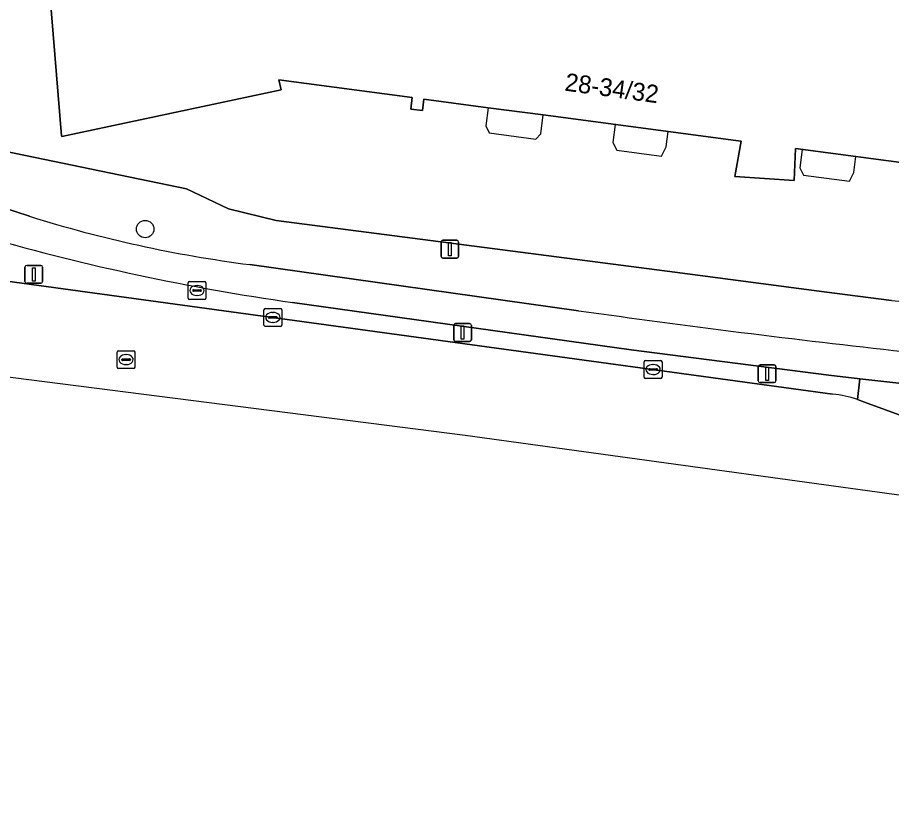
# Model space of a CAD drawing. Extents: x 160675 to 161153, y 383241 to 383714.
# Drawn here: x 160724.18 to 160773.22, y 383263.09 to 383306.84 of the extents above; entities that cross this region are included whole.
import ezdxf

# ---------------------------------------------------------------- set-up
doc = ezdxf.new("R2010")
doc.units = 0
for name, color, linetype in [('IMGEO_Berm_open', 7, 'Continuous'), ('IMGEO_Boom', 7, 'Continuous'), ('IMGEO_Fietspad_gesloten', 7, 'Continuous'), ('IMGEO_Groenvoorziening', 7, 'Continuous'), ('IMGEO_Kolk', 7, 'Continuous'), ('IMGEO_Lichtmast', 7, 'Continuous'), ('IMGEO_Pand', 7, 'Continuous'), ('IMGEO_Pand_nummerreeks', 7, 'Continuous'), ('IMGEO_Pand_overbouw', 7, 'Continuous'), ('IMGEO_Rijbaan_lokaal_gesloten', 7, 'Continuous'), ('IMGEO_Rioolput', 7, 'Continuous'), ('IMGEO_Voetpad_open', 7, 'Continuous')]:
    doc.layers.add(name, color=color, linetype=linetype)

msp = doc.modelspace()

# ---------------------------------------------------------------- linework, layer by layer
at = {"layer": 'IMGEO_Berm_open'}
for points in [[(160720.857, 383292.423), (160769.912, 383285.718)], [(160771.308, 383285.419), (160771.45, 383286.574), (160769.706, 383286.77), (160758.605, 383288.201), (160739.615, 383290.854)]]:
    msp.add_lwpolyline(points, dxfattribs=at)
for centre, radius, start, end in [((160757.689, 383417.561), 127.99, 254.03333, 261.88177), ((160769.234, 383279.143), 6.61, 71.7112, 84.1105)]:
    msp.add_arc(centre, radius, start, end, dxfattribs=at)
at = {"layer": 'IMGEO_Boom'}
msp.add_circle((160731.347, 383294.972), 0.489, dxfattribs=at)
at = {"layer": 'IMGEO_Fietspad_gesloten'}
for points in [[(160724.863, 383295.69), (160719.204, 383297.531)], [(160755.662, 383290.395), (160737.228, 383292.98)], [(160739.615, 383290.854), (160758.605, 383288.201), (160769.706, 383286.77), (160771.45, 383286.574), (160777.852, 383285.853), (160783.082, 383285.264), (160794.632, 383283.749), (160799.634, 383283.067), (160810.848, 383281.538), (160816.508, 383280.767), (160828.488, 383279.134), (160834.185, 383278.357), (160852.13, 383275.911), (160857.577, 383275.169), (160873.203, 383273.039)]]:
    msp.add_lwpolyline(points, dxfattribs=at)
for centre, radius, start, end in [((160746.363, 383364.222), 71.826, 252.58268, 262.69355), ((160757.689, 383417.561), 127.99, 254.03333, 261.88177), ((160838.878, 383879.339), 594.794, 261.957551, 263.729038)]:
    msp.add_arc(centre, radius, start, end, dxfattribs=at)
at = {"layer": 'IMGEO_Groenvoorziening'}
for points in [[(160774.882, 383298.555), (160767.84, 383299.49), (160767.765, 383297.687), (160764.421, 383297.914), (160764.421, 383297.916), (160764.788, 383299.895), (160764.483, 383299.936), (160753.68, 383301.37), (160750.598, 383301.779), (160746.986, 383302.258), (160746.904, 383301.62), (160746.246, 383301.706), (160746.332, 383302.345), (160738.853, 383303.338), (160738.971, 383302.787), (160726.669, 383300.167), (160726.644, 383300.199), (160724.272, 383329.175)], [(160720.042, 383300.069), (160720.82, 383299.881), (160733.661, 383297.23), (160736.023, 383296.113), (160738.693, 383295.459), (160761.067, 383292.551), (160769.45, 383291.461), (160773.221, 383290.971)]]:
    msp.add_lwpolyline(points, dxfattribs=at)
msp.add_lwpolyline([(160777.852, 383285.853), (160771.45, 383286.574), (160771.308, 383285.419), (160771.71, 383285.271), (160777.187, 383283.264), (160777.552, 383283.158)], close=True, dxfattribs=at)
msp.add_arc((160774.582, 383301.91), 11.023, 262.9096, 313.4171, dxfattribs=at)
at = {"layer": 'IMGEO_Kolk'}
for p, q in [((160738.011, 383289.59), (160738.011, 383290.442)), ((160738.086, 383290.516), (160738.938, 383290.516)), ((160739.012, 383290.442), (160739.012, 383289.59)), ((160738.27, 383290.01), (160738.27, 383290.022)), ((160738.708, 383289.973), (160738.31, 383289.973)), ((160738.313, 383290.059), (160738.711, 383290.059)), ((160738.499, 383290.296), (160738.524, 383290.296)), ((160738.754, 383290.022), (160738.754, 383290.01)), ((160738.938, 383289.516), (160738.086, 383289.516)), ((160738.522, 383289.736), (160738.497, 383289.736)), ((160759.344, 383286.669), (160759.344, 383287.521)), ((160759.419, 383287.595), (160760.271, 383287.595)), ((160760.345, 383287.521), (160760.345, 383286.669)), ((160759.603, 383287.089), (160759.603, 383287.101)), ((160760.041, 383287.052), (160759.643, 383287.052)), ((160759.646, 383287.138), (160760.044, 383287.138)), ((160759.832, 383287.375), (160759.857, 383287.375)), ((160760.087, 383287.101), (160760.087, 383287.089)), ((160760.271, 383286.595), (160759.419, 383286.595)), ((160759.855, 383286.815), (160759.83, 383286.815))]:
    msp.add_line(p, q, dxfattribs=at)
for points in [[(160738.011, 383289.59), (160738.011, 383290.442)], [(160738.086, 383290.516), (160738.938, 383290.516)], [(160739.012, 383290.442), (160739.012, 383289.59)], [(160738.938, 383289.516), (160738.086, 383289.516)], [(160759.344, 383286.669), (160759.344, 383287.521)], [(160759.419, 383287.595), (160760.271, 383287.595)], [(160760.345, 383287.521), (160760.345, 383286.669)], [(160760.271, 383286.595), (160759.419, 383286.595)]]:
    msp.add_lwpolyline(points, dxfattribs=at)
for centre, radius, start, end in [((160738.088, 383290.44), 0.0765, 91.552, 178.448), ((160738.088, 383290.44), 0.0765, 91.552, 178.448), ((160738.936, 383290.44), 0.0765, 1.552, 88.448), ((160738.936, 383290.44), 0.0765, 1.552, 88.448), ((160738.31, 383290.019), 0.0403, 85.8775, 175.7526), ((160738.307, 383290.009), 0.0366, 178.938, 274.7102), ((160738.711, 383290.016), 0.043, 264.8664, 352.4533), ((160738.715, 383290.021), 0.0386, 1.7309, 96.639), ((160738.088, 383289.592), 0.0765, 181.552, 268.448), ((160738.088, 383289.592), 0.0765, 181.552, 268.448), ((160738.936, 383289.592), 0.0765, 271.552, 358.448), ((160738.936, 383289.592), 0.0765, 271.552, 358.448), ((160759.421, 383287.519), 0.0765, 91.552, 178.448), ((160759.421, 383287.519), 0.0765, 91.552, 178.448), ((160760.269, 383287.519), 0.0765, 1.552, 88.448), ((160760.269, 383287.519), 0.0765, 1.552, 88.448), ((160759.643, 383287.098), 0.0403, 85.8775, 175.7526), ((160759.64, 383287.088), 0.0366, 178.938, 274.7102), ((160760.044, 383287.095), 0.043, 264.8664, 352.4533), ((160760.048, 383287.1), 0.0386, 1.7309, 96.639), ((160759.421, 383286.671), 0.0765, 181.552, 268.448), ((160759.421, 383286.671), 0.0765, 181.552, 268.448), ((160760.269, 383286.671), 0.0765, 271.552, 358.448), ((160760.269, 383286.671), 0.0765, 271.552, 358.448)]:
    msp.add_arc(centre, radius, start, end, dxfattribs=at)
for centre, major_axis, ratio, start_param, end_param in [((160738.498, 383290.016), (-0.387, 0.002), 0.722429, 4.712389, 7.853982), ((160738.523, 383290.016), (-0.39, 0.002), 0.717154, 1.570796, 4.712389), ((160759.831, 383287.095), (-0.387, 0.002), 0.722429, 4.712389, 7.853982), ((160759.856, 383287.095), (-0.39, 0.002), 0.717154, 1.570796, 4.712389)]:
    msp.add_ellipse(centre, major_axis=major_axis, ratio=ratio, start_param=start_param, end_param=end_param, dxfattribs=at)
at = {"layer": 'IMGEO_Lichtmast'}
for p, q in [((160748.045, 383294.341), (160748.835, 383294.341)), ((160748.835, 383294.341), (160748.045, 383294.341)), ((160747.945, 383293.441), (160747.945, 383294.241)), ((160747.945, 383294.241), (160747.945, 383293.441)), ((160748.935, 383294.241), (160748.935, 383293.441)), ((160748.935, 383293.441), (160748.935, 383294.241)), ((160748.835, 383293.341), (160748.045, 383293.341)), ((160748.045, 383293.341), (160748.835, 383293.341)), ((160724.601, 383292.031), (160724.601, 383292.831)), ((160724.601, 383292.831), (160724.601, 383292.031)), ((160724.701, 383292.931), (160725.491, 383292.931)), ((160725.491, 383292.931), (160724.701, 383292.931)), ((160725.591, 383292.831), (160725.591, 383292.031)), ((160725.591, 383292.031), (160725.591, 383292.831)), ((160725.491, 383291.931), (160724.701, 383291.931)), ((160724.701, 383291.931), (160725.491, 383291.931)), ((160748.661, 383288.768), (160748.661, 383289.568)), ((160748.661, 383289.568), (160748.661, 383288.768)), ((160748.761, 383289.668), (160749.551, 383289.668)), ((160749.551, 383289.668), (160748.761, 383289.668)), ((160749.651, 383289.568), (160749.651, 383288.768)), ((160749.651, 383288.768), (160749.651, 383289.568)), ((160749.551, 383288.668), (160748.761, 383288.668)), ((160748.761, 383288.668), (160749.551, 383288.668)), ((160765.743, 383286.458), (160765.743, 383287.258)), ((160765.743, 383287.258), (160765.743, 383286.458)), ((160765.843, 383287.358), (160766.633, 383287.358)), ((160766.633, 383287.358), (160765.843, 383287.358)), ((160766.733, 383287.258), (160766.733, 383286.458)), ((160766.733, 383286.458), (160766.733, 383287.258)), ((160766.633, 383286.358), (160765.843, 383286.358)), ((160765.843, 383286.358), (160766.633, 383286.358))]:
    msp.add_line(p, q, dxfattribs=at)
for points in [[(160748.365, 383294.216), (160748.515, 383294.216), (160748.515, 383293.466), (160748.365, 383293.466), (160748.365, 383294.216)], [(160725.021, 383292.806), (160725.171, 383292.806), (160725.171, 383292.056), (160725.021, 383292.056), (160725.021, 383292.806)], [(160749.081, 383289.543), (160749.231, 383289.543), (160749.231, 383288.793), (160749.081, 383288.793), (160749.081, 383289.543)], [(160766.163, 383287.233), (160766.313, 383287.233), (160766.313, 383286.483), (160766.163, 383286.483), (160766.163, 383287.233)]]:
    msp.add_lwpolyline(points, dxfattribs=at)
for centre, start, end in [((160748.045, 383294.241), 90, 180), ((160748.045, 383294.241), 90, 180), ((160748.835, 383294.241), 0, 90), ((160748.835, 383294.241), 360, 90), ((160748.045, 383293.441), 180, 270), ((160748.045, 383293.441), 180, 270), ((160748.835, 383293.441), 270, 0), ((160748.835, 383293.441), 270, 0), ((160724.701, 383292.831), 90, 180), ((160724.701, 383292.831), 90, 180), ((160725.491, 383292.831), 0, 90), ((160725.491, 383292.831), 360, 90), ((160724.701, 383292.031), 180, 270), ((160724.701, 383292.031), 180, 270), ((160725.491, 383292.031), 270, 0), ((160725.491, 383292.031), 270, 0), ((160748.761, 383289.568), 90, 180), ((160748.761, 383289.568), 90, 180), ((160749.551, 383289.568), 0, 90), ((160749.551, 383289.568), 360, 90), ((160748.761, 383288.768), 180, 270), ((160748.761, 383288.768), 180, 270), ((160749.551, 383288.768), 270, 0), ((160749.551, 383288.768), 270, 0), ((160765.843, 383287.258), 90, 180), ((160765.843, 383287.258), 90, 180), ((160766.633, 383287.258), 0, 90), ((160766.633, 383287.258), 360, 90), ((160765.843, 383286.458), 180, 270), ((160765.843, 383286.458), 180, 270), ((160766.633, 383286.458), 270, 0), ((160766.633, 383286.458), 270, 0)]:
    msp.add_arc(centre, 0.1, start, end, dxfattribs=at)
at = {"layer": 'IMGEO_Pand'}
msp.add_lwpolyline([(160724.272, 383329.175), (160726.644, 383300.199), (160726.669, 383300.167), (160738.971, 383302.787), (160738.853, 383303.338), (160746.332, 383302.345), (160746.246, 383301.706), (160746.904, 383301.62), (160746.986, 383302.258), (160750.598, 383301.779), (160753.68, 383301.37), (160764.483, 383299.936), (160764.788, 383299.895), (160764.421, 383297.916), (160764.421, 383297.914), (160767.765, 383297.687), (160767.84, 383299.49), (160774.882, 383298.555)], dxfattribs=at)
at = {"layer": 'IMGEO_Pand_overbouw'}
for points in [[(160753.68, 383301.37), (160750.598, 383301.779), (160750.464, 383300.766), (160750.644, 383300.362), (160753.27, 383300.013), (160753.538, 383300.306)], [(160757.718, 383300.834), (160757.584, 383299.826), (160757.819, 383299.393), (160760.323, 383299.061), (160760.584, 383299.575), (160760.699, 383300.438)], [(160768.212, 383299.441), (160768.074, 383298.406), (160768.28, 383297.996), (160770.858, 383297.654), (160771.098, 383298.152), (160771.216, 383299.042)]]:
    msp.add_lwpolyline(points, close=True, dxfattribs=at)
at = {"layer": 'IMGEO_Rijbaan_lokaal_gesloten'}
for points in [[(160769.912, 383285.718), (160720.857, 383292.423), (160716.095, 383293.073), (160715.848, 383293.119), (160712.137, 383293.632), (160711.352, 383293.738), (160711.332, 383290.596), (160711.318, 383288.264), (160749.307, 383283.418), (160760.039, 383281.939), (160789.689, 383277.854), (160896.852, 383263.09)], [(160896.852, 383263.09), (160897.357, 383266.625), (160878.574, 383269.26), (160875.826, 383269.639), (160875.72, 383269.65), (160872.814, 383270.055), (160872.393, 383270.131), (160855.077, 383272.545), (160854.652, 383272.548), (160831.433, 383275.789), (160830.95, 383275.871), (160813.66, 383278.199), (160813.035, 383278.32), (160800.901, 383279.923), (160799.302, 383280.124), (160799.145, 383280.144), (160778.824, 383282.894), (160778.227, 383282.961), (160777.552, 383283.158), (160777.187, 383283.264), (160771.71, 383285.271), (160771.308, 383285.419)]]:
    msp.add_lwpolyline(points, dxfattribs=at)
msp.add_arc((160769.234, 383279.143), 6.61, 71.7112, 84.1105, dxfattribs=at)
at = {"layer": 'IMGEO_Rioolput'}
for p, q in [((160733.757, 383291.1), (160733.757, 383291.952)), ((160733.832, 383292.026), (160734.684, 383292.026)), ((160734.245, 383291.806), (160734.27, 383291.806)), ((160734.758, 383291.952), (160734.758, 383291.1)), ((160734.016, 383291.52), (160734.016, 383291.532)), ((160734.454, 383291.483), (160734.056, 383291.483)), ((160734.059, 383291.569), (160734.457, 383291.569)), ((160734.5, 383291.532), (160734.5, 383291.52)), ((160734.684, 383291.026), (160733.832, 383291.026)), ((160734.268, 383291.246), (160734.243, 383291.246)), ((160729.775, 383287.225), (160729.775, 383288.077)), ((160729.85, 383288.151), (160730.702, 383288.151)), ((160730.263, 383287.931), (160730.288, 383287.931)), ((160730.776, 383288.077), (160730.776, 383287.225)), ((160730.034, 383287.645), (160730.034, 383287.657)), ((160730.472, 383287.608), (160730.074, 383287.608)), ((160730.077, 383287.694), (160730.475, 383287.694)), ((160730.518, 383287.657), (160730.518, 383287.645)), ((160730.702, 383287.151), (160729.85, 383287.151)), ((160730.286, 383287.371), (160730.261, 383287.371))]:
    msp.add_line(p, q, dxfattribs=at)
for points in [[(160733.757, 383291.1), (160733.757, 383291.952)], [(160733.832, 383292.026), (160734.684, 383292.026)], [(160734.758, 383291.952), (160734.758, 383291.1)], [(160734.684, 383291.026), (160733.832, 383291.026)], [(160729.775, 383287.225), (160729.775, 383288.077)], [(160729.85, 383288.151), (160730.702, 383288.151)], [(160730.776, 383288.077), (160730.776, 383287.225)], [(160730.702, 383287.151), (160729.85, 383287.151)]]:
    msp.add_lwpolyline(points, dxfattribs=at)
for centre, radius, start, end in [((160733.834, 383291.95), 0.0765, 91.552, 178.448), ((160733.834, 383291.95), 0.0765, 91.552, 178.448), ((160734.682, 383291.95), 0.0765, 1.552, 88.448), ((160734.682, 383291.95), 0.0765, 1.552, 88.448), ((160734.056, 383291.529), 0.0403, 85.8775, 175.7526), ((160734.053, 383291.519), 0.0366, 178.938, 274.7102), ((160734.457, 383291.526), 0.043, 264.8664, 352.4533), ((160734.461, 383291.531), 0.0386, 1.7309, 96.639), ((160733.834, 383291.102), 0.0765, 181.552, 268.448), ((160733.834, 383291.102), 0.0765, 181.552, 268.448), ((160734.682, 383291.102), 0.0765, 271.552, 358.448), ((160734.682, 383291.102), 0.0765, 271.552, 358.448), ((160729.852, 383288.075), 0.0765, 91.552, 178.448), ((160729.852, 383288.075), 0.0765, 91.552, 178.448), ((160730.7, 383288.075), 0.0765, 1.552, 88.448), ((160730.7, 383288.075), 0.0765, 1.552, 88.448), ((160730.074, 383287.654), 0.0403, 85.8775, 175.7526), ((160730.071, 383287.644), 0.0366, 178.938, 274.7102), ((160730.475, 383287.651), 0.043, 264.8664, 352.4533), ((160730.479, 383287.656), 0.0386, 1.7309, 96.639), ((160729.852, 383287.227), 0.0765, 181.552, 268.448), ((160729.852, 383287.227), 0.0765, 181.552, 268.448), ((160730.7, 383287.227), 0.0765, 271.552, 358.448), ((160730.7, 383287.227), 0.0765, 271.552, 358.448)]:
    msp.add_arc(centre, radius, start, end, dxfattribs=at)
for centre, major_axis, ratio, start_param, end_param in [((160734.244, 383291.526), (-0.387, 0.002), 0.722429, 4.712389, 7.853982), ((160734.269, 383291.526), (-0.39, 0.002), 0.717154, 1.570796, 4.712389), ((160730.262, 383287.651), (-0.387, 0.002), 0.722429, 4.712389, 7.853982), ((160730.287, 383287.651), (-0.39, 0.002), 0.717154, 1.570796, 4.712389)]:
    msp.add_ellipse(centre, major_axis=major_axis, ratio=ratio, start_param=start_param, end_param=end_param, dxfattribs=at)
at = {"layer": 'IMGEO_Voetpad_open'}
for points in [[(160761.067, 383292.551), (160738.693, 383295.459), (160736.023, 383296.113), (160733.661, 383297.23), (160720.82, 383299.881), (160720.042, 383300.069)], [(160719.204, 383297.531), (160724.863, 383295.69)], [(160737.228, 383292.98), (160755.662, 383290.395)], [(160773.221, 383290.971), (160769.45, 383291.461), (160761.067, 383292.551)]]:
    msp.add_lwpolyline(points, dxfattribs=at)
for centre, radius, start, end in [((160746.363, 383364.222), 71.826, 252.58268, 262.69355), ((160774.582, 383301.91), 11.023, 262.9096, 313.4171), ((160838.878, 383879.339), 594.794, 261.957551, 263.729038)]:
    msp.add_arc(centre, radius, start, end, dxfattribs=at)

# ---------------------------------------------------------------- texts
at = {"layer": 'IMGEO_Pand_nummerreeks'}
msp.add_text('28-34/32', height=1, rotation=352.2422, dxfattribs=at).set_placement((160754.85, 383302.741))

doc.saveas('drawing.dxf')
